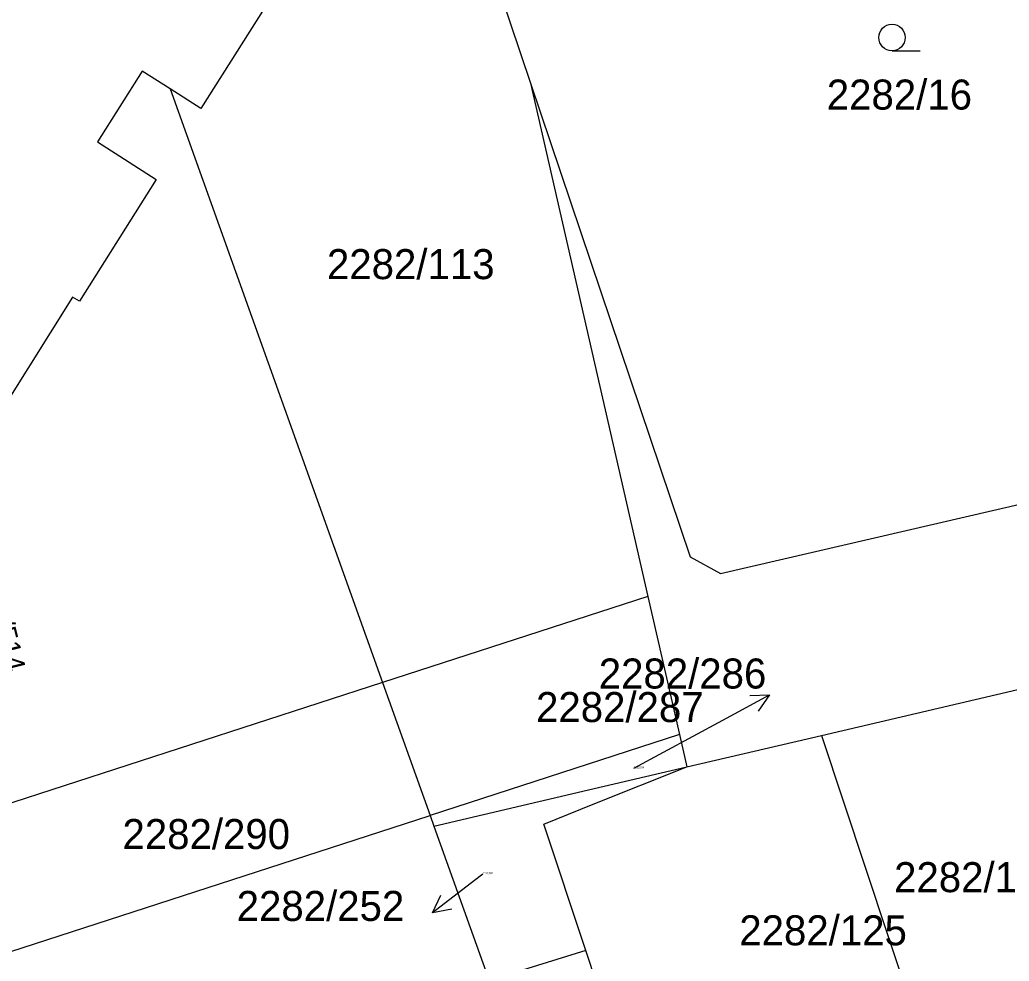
# Model space of a CAD drawing. Extents: x -785744 to -782822, y -1067550 to -1063910.
# Drawn here: x -783857.9 to -783802, y -1066065.2 to -1066011.9 of the extents above; entities that cross this region are included whole.
import ezdxf

# ---------------------------------------------------------------- set-up
doc = ezdxf.new("R2010")
doc.units = 0
for name, color, linetype in [('Hranice parcel', 7, 'Continuous'), ('Parcelní čísla', 7, 'Continuous'), ('Pop_ČP_popisy', 7, 'Continuous'), ('Značky kultur', 7, 'Continuous')]:
    doc.layers.add(name, color=color, linetype=linetype)

msp = doc.modelspace()

# ---------------------------------------------------------------- linework, layer by layer
at = {"layer": 'Hranice parcel'}
for p, q in [((-783843.33, -1066009.97), (-783847.69, -1066016.87)), ((-783829.04, -1066015.45), (-783822.41, -1066044.5)), ((-783847.69, -1066016.87), (-783849.44, -1066015.77)), ((-783822.41, -1066044.5), (-783837.42, -1066049.37)), ((-783822.41, -1066044.5), (-783820.62, -1066052.33)), ((-783837.42, -1066049.37), (-783834.72, -1066056.91)), ((-783820.62, -1066052.33), (-783834.72, -1066056.91)), ((-783820.62, -1066052.33), (-783820.2, -1066054.16)), ((-783825.5, -1066056.27), (-783820.2, -1066054.16)), ((-783863.88, -1066066.38), (-783834.72, -1066056.91)), ((-783834.72, -1066056.91), (-783834.51, -1066057.51)), ((-783834.51, -1066057.51), (-783831.38, -1066066.25)), ((-783825.92, -1066064.55), (-783831.38, -1066066.25)), ((-783821.12, -1066078.99), (-783825.92, -1066064.55))]:
    msp.add_line(p, q, dxfattribs=at)
for points in [[(-783840.14, -1065982.5), (-783829.04, -1066015.45)], [(-783851.02, -1066014.77), (-783853.54, -1066018.77)], [(-783849.44, -1066015.77), (-783851.02, -1066014.77)], [(-783829.04, -1066015.45), (-783820.01, -1066042.27)], [(-783818.3, -1066043.2), (-783698.83, -1066015.52)], [(-783849.44, -1066015.77), (-783837.42, -1066049.37)], [(-783853.54, -1066018.77), (-783850.22, -1066020.9)], [(-783850.22, -1066020.9), (-783854.56, -1066027.78)], [(-783854.95, -1066027.56), (-783858.75, -1066033.62)], [(-783854.56, -1066027.78), (-783854.95, -1066027.56)], [(-783820.01, -1066042.27), (-783818.3, -1066043.2)], [(-783812.57, -1066052.37), (-783799.37, -1066049.28)], [(-783837.42, -1066049.37), (-783866.26, -1066058.74)], [(-783820.2, -1066054.16), (-783812.57, -1066052.37)], [(-783812.57, -1066052.37), (-783803.82, -1066078.78)], [(-783825.77, -1066055.46), (-783820.2, -1066054.16)], [(-783834.51, -1066057.51), (-783825.77, -1066055.46)], [(-783828.29, -1066057.4), (-783825.5, -1066056.27)], [(-783825.92, -1066064.55), (-783828.29, -1066057.4)]]:
    msp.add_lwpolyline(points, dxfattribs=at)
at = {"layer": 'Pop_ČP_popisy'}
for p, q in [((-783818.16, -1066051.51), (-783815.523, -1066050.079)), ((-783832.22, -1066060.59), (-783834.593, -1066062.426))]:
    msp.add_line(p, q, dxfattribs=at)
for points in [[(-783816.641, -1066050.117), (-783815.523, -1066050.079), (-783816.164, -1066050.996)], [(-783823.19, -1066054.23), (-783818.16, -1066051.51)], [(-783831.75, -1066060.23), (-783832.22, -1066060.59)], [(-783833.496, -1066062.209), (-783834.593, -1066062.426), (-783834.108, -1066061.418)]]:
    msp.add_lwpolyline(points, dxfattribs=at)
at = {"layer": 'Značky kultur'}
msp.add_line((-783808.59, -1066013.61), (-783806.99, -1066013.61), dxfattribs=at)
msp.add_circle((-783808.59, -1066012.86), 0.75, dxfattribs=at)

# ---------------------------------------------------------------- texts
at = {"layer": 'Parcelní čísla'}
for s, height, p in [('2282/16', 1.7, (-783812.28, -1066016.94)), ('2282/113', 1.7, (-783840.56, -1066026.54)), ('2282/287', 1.7, (-783828.73, -1066051.62)), ('2282/286', 0.1, (-783823.19, -1066054.23)), ('2282/290', 1.7, (-783852.13, -1066058.81)), ('2282/124', 1.7, (-783808.47, -1066061.25)), ('2282/252', 0.1, (-783831.75, -1066060.23)), ('2282/125', 1.7, (-783817.23, -1066064.26))]:
    msp.add_text(s, height=height, dxfattribs=at).set_placement(p)
at = {"layer": 'Pop_ČP_popisy'}
msp.add_text('2282/514', height=1.14, rotation=284.1643, dxfattribs=at).set_placement((-783860.249, -1066042.675))
for s, p in [('2282/286', (-783825.182, -1066049.72)), ('2282/252', (-783845.668, -1066062.88))]:
    msp.add_text(s, height=1.7, dxfattribs=at).set_placement(p)

doc.saveas('drawing.dxf')
